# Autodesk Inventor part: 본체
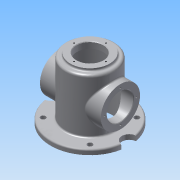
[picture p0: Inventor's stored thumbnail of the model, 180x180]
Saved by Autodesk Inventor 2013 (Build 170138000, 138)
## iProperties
Created: 2018-04
Part Number: 본체
Material: 알루미늄 6061
Document SubType Name: Modeling
Designer: Administrator
Density: 2.71 g/cm^3
Mass: 1152.89 g
Surface Area: 1204.3 cm^2
Volume: 425.422 cm^3
Author: Administrator
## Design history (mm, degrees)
sketch "스케치1"
  geometry: C1 r 80 at (0, 0); 1 further point
  constraints: 1 centre point, 1 coincident
  dimensions: "d2" = 160 diameter of C1
extrude "돌출1" new body sketch "스케치1" distance "d4" = 10; taper "d5" = 0 deg
sketch "스케치2"
  geometry: C1 r 15 at (80, 0); C2 r 15 at (-80, 0); A1 r 80 centre (0, 0) between (80, 0) and (-80, 0) reference
  constraints: 2 centre point, 2 horizontal alignment, 2 point on circle, 1 equal radius
  dimensions: "d6" = 30 diameter of C1
extrude "돌출2" cut sketch "스케치2" distance "d8" = 10; taper "d9" = 0 deg
node "작업 평면1"
sketch "스케치3"
  geometry: L1 (0, 10)-(0, 125); L2 (0, 125)-(40, 125); L3 (78.594, 10)-(-78.594, 10) reference; L4 (40, 125)-(40, 120); L5 (40, 120)-(50, 120); L6 (50, 120)-(50, 10); 3 further points
  constraints: 10 end point, 4 midpoint, 4 perpendicular, 2 point on line, 1 vertical
  dimensions: "d19" = 100 diameter of L6 L1; "d21" = 80 diameter of L4 L1; "d23" = 5 distance of L2.end L4.end; "d30" = 110 distance between parallel lines of L3 L5
revolve "회전1" sketch "스케치3" stored, may be unused: angle "d24" = 90 deg
node "작업 평면2"
sketch "스케치4"
  geometry: L1 (-50, 120)-(50, 120) reference; L2 (14.934, 0)-(80, 0) reference; C1 r 40 at (0, 60); 2 further points
  constraints: 1 centre point, 1 midpoint, 1 vertical alignment
  dimensions: "d26" = 60 distance from line of L2 C1.centre; "d27" = 80 diameter of C1
extrude "돌출3" join sketch "스케치4" stored distance "d28" = 10; taper "d29" = 0 deg
sketch "스케치5" dims "d31" = 65
  geometry: C1 r 40 at (0, 0) reference; 3 further points
  constraints: 2 vertical alignment, 1 coincident, 2 other
hole "구멍1" sketch "스케치5" at (0, 32.5) diameter "d33" = 3.242; stored, may be unused: countersink angle "d37" = 90 deg, drill point angle "d39" = 118 deg; dims "d34" = 8, "d35" = 4, "d36" = 2, "d38" = 10
node "작업 평면3"
hole "구멍2" diameter "d46" = 54; stored, may be unused: countersink angle "d50" = 90 deg, drill point angle "d52" = 118 deg; dims "d44" = 10, "d45" = 10, "d47" = 8, "d48" = 4, "d49" = 2, "d51" = 10
node "작업 평면4"
sketch "스케치6"
  geometry: 1 further point
sketch "스케치7"
  geometry: L1 (0, 0)-(0, -8); L2 (-78.594, 0)-(78.594, 0) reference; L3 (0, -8)-(50, -8); L4 (50, -8)-(50, 0); 1 further point
  constraints: 6 end point, 1 midpoint, 1 parallel, 1 perpendicular, 1 point on line, 1 vertical
  dimensions: "d54" = 8 distance of L1.end L1.start; "d56" = 100 diameter of L4 L1
revolve "회전2" sketch "스케치7" stored, may be unused: angle "d57" = 90 deg
sketch "스케치8"
  geometry: L1 (-40, 125)-(40, 125) reference; L2 (-50, -8)-(50, -8) reference; L3 (0, 125)-(0, -8); L4 (27, 125)-(27, 112); L5 (27, 112)-(45, 112); L6 (45, 112)-(45, -8); L7 (27, 125)-(0, 125); L8 (0, -8)-(45, -8); 1 further point
  constraints: 12 end point, 2 midpoint, 2 perpendicular, 2 point on line, 1 collinear, 1 parallel
  dimensions: "d58" = 54 diameter of L4 L3; "d60" = 13 distance of L4.start L4.end; "d61" = 90 diameter of L6 L3
revolve "회전3" sketch "스케치8" stored, may be unused: angle "d62" = 90 deg
sketch "스케치9"
  geometry: L1 (0, 0)-(0, 67.5); L2 (0, 0)-(-47.73, 47.73); A1 r 80 centre (0, 0) between (78.594, 14.934) and (-78.594, 14.934) reference; A2 r 67.5 centre (0, 0) between (0, 67.5) and (-47.73, 47.73); 1 further point
  constraints: 4 end point, 2 coincident, 2 point on circle, 1 centre point, 1 vertical
  dimensions: "d63" = 135 diameter of A2; "d65" = 45 deg angle of L2 L1
hole "구멍3" sketch "스케치9" at (-47.73, 47.73) diameter "d67" = 10; stored, may be unused: countersink angle "d71" = 90 deg, drill point angle "d73" = 118 deg; dims "d68" = 8, "d69" = 4, "d70" = 2, "d72" = 10
node "작업 평면5"
sketch "스케치10" dims "d78" = 65
  geometry: C1 r 27 at (0, 0) reference; C2 r 40 at (0, 0) reference; 2 further points
  constraints: 2 vertical alignment, 1 coincident, 2 other
hole "구멍4" sketch "스케치10" at (0, 32.5) diameter "d81" = 3.242; stored, may be unused: countersink angle "d85" = 90 deg, drill point angle "d87" = 118 deg; dims "d82" = 8, "d83" = 4, "d84" = 2, "d86" = 10
fillet "모깎기1" dims "d91" = 3, "d92" = 5
fillet "모깎기2" dims "d93" = 3
chamfer "모따기1" distance "d94" = 1; stored, may be unused: second distance "d95" = 2, angle "d96" = 45 deg
fillet "모깎기3" dims "d97" = 3
chamfer "모따기2" distance "d98" = 1; stored, may be unused: second distance "d99" = 2, angle "d100" = 45 deg
node "작업 평면6"
node "작업 평면7"
sketch "스케치12"
  geometry: L1 (-78.594, 0)-(78.594, 0) reference; 3 further points
  constraints: 1 midpoint, 1 vertical alignment, 1 other
  dimensions: "d106" = 70 distance from line of L1 point (0, 70)
feature "엠보싱2" sketch "스케치12" dims "d19" = 100, "d21" = 80, "d23" = 5, "d30" = 110, "d107" = 0.5, "d108" = 0
node "솔리드1"
pattern_circular "원형 패턴1" dims angle "d41" = 360 deg
mirror "대칭1"
pattern_circular "원형 패턴2" dims angle "d75" = 360 deg
mirror "대칭2"
pattern_circular "원형 패턴3" dims angle "d89" = 360 deg
other parameters: "d10" = 0, "d25" = 62, "d43" = 0, "d53" = 0, "d77" = 0, "d101" = -83, "d105" = 67.25
